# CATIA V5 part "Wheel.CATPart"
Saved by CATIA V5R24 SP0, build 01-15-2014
Part number: Wheel
Bounding box of the stored display mesh (mm): x -49.986 to 49.986, y -49.986 to 49.986, z -22.5 to 22.5
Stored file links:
  \\cdl-main\FTPSERVER\Minsik\2016\2\Wheel.CATPart
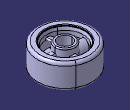
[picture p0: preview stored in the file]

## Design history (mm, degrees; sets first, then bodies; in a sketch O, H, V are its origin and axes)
Set1
  Sketch1 on yz-plane, origin (0, 0, 0), H (0, 1, 0), V (0, 0, 1)
    axis line L1 (0, 45.4444) -> (0, -46.7173)
    point P1 (0, 45.4444)
    point P3 (32, -5.5)
    line L2 (32, -5.5) -> (32, -18)
    line L3 (32, -18) -> (34, -18)
    line L4 (34, -18) -> (34, -21.4393)
    line L5 (35.0607, -22.5) -> (45, -22.5)
    line L6 (50, -17.5) -> (50, 17.5)
    line L7 (45, 22.5) -> (37.5, 22.5)
    line L8 (36.5, 21.5) -> (36.5, 20.5)
    line L9 (36.5, 20.5) -> (35.5, 20.5)
    point P7 (35.5, 20.5)
    line L10 (35.5, 20.5) -> (33.5, 15.5)
    point P8 (33.5, 15.5)
    line L11 (33.5, 15.5) -> (33.5, 7.5)
    point P9 (33.5, 7.5)
    line L12 (33.5, 7.5) -> (32, -5.5)
    arc A1 centre (45, 17.5) radius 5 from (45, 22.5) to (50, 17.5) cw
    arc A2 centre (45, -17.5) radius 5 from (50, -17.5) to (45, -22.5) cw
    arc A3 centre (37.5, 21.5) radius 1 from (37.5, 22.5) to (36.5, 21.5) ccw
    line L13 (34, -21.4393) -> (35.0607, -22.5)
    distance L5 L7 = 45
    distance L6 V = 50
    distance L11 V = 33.5
    distance L7 L9 = 2
    length L9 = 1
    distance L11 P7 = 2
    distance L9 P8 = 5
    distance L3 L5 = 4.5
    distance L7 P9 = 15
    distance P9 P3 V = 13
    distance L2 L4 = 2
    radius A1 = 5
    radius A2 = 5
    radius A3 = 1
    angle L4 L13 = 45
    length L13 = 1.5
    distance L2 V = 32
    coincidence: P1 V
    vertical: L1 V, L2 V, L4 V, L6 V, L8 V, L11 V
    horizontal: L3 H, L5 H, L7 H, L9 H
    symmetry: L7 L5 H
    tangency: A1 L7, A1 L6, A2 L6, A2 L5, A3 L7, A3 L8
Body1 (main body)
  Shaft1: profile Sketch1, axis Sketch1.L1, angle 360
  Sketch2 on xy-plane, origin (0, 0, 0), H (1, 0, 0), V (0, 1, 0)
    circle A1 centre (0, 0) radius 18
    circle A2 centre (0, 0) radius 12.5
    radius A1 = 18
    radius A2 = 12.5
  Pad1: profile Sketch2, direction (0, 0, 1), length 22.5, mirrored extent
  Fillet1: radius 2, on edge [face of Pad1 from Sketch2.A1 | end face of Pad1]
  Sketch3 on xy-plane, origin (0, 0, 0), H (1, 0, 0), V (0, 1, 0)
    circle A1 centre (0, 0) radius 40
    circle A2 centre (0, 0) radius 14
    radius A1 = 40
    radius A2 = 14
  Pad2: profile Sketch3, direction (0, 0, 1), length -5.5, opposite side length 14
  Sketch4 on start face of Pad2, origin (0, 0, -14), H (1, 0, 0), V (0, -1, 0)
    construction arc A1 centre (3, 10) radius 20 from (-3, 29.0788) to (-16.5, 14.4441) ccw
    point P1 (3, 10)
    point P2 (-3, 29.0788)
    point P3 (-16.5, 14.4441)
    arc A2 centre (-3, 29.0788) radius 1.5 from (-3.45, 30.5097) to (-2.55, 27.6479) cw
    arc A3 centre (-16.5, 14.4441) radius 1.5 from (-15.0375, 14.1108) to (-17.9625, 14.7774) cw
    arc A4 centre (3, 10) radius 18.5 from (-2.55, 27.6479) to (-15.0375, 14.1108) ccw
    arc A5 centre (3, 10) radius 21.5 from (-17.9625, 14.7774) to (-3.45, 30.5097) cw
    radius A3 = 1.5
    distance P2 V = 3
    radius A5 = 21.5
    distance P1 H = 10
    distance P1 V = 3
    distance P3 V = 16.5
    tangency: A4 A3, A3 A5, A5 A2, A2 A4
    concentricity: A4 P1, A5 P1
  Pocket1: profile Sketch4, direction (0, 0, 1), through (limit type 6)
  CircPattern1: of Pocket1, instances 7, angular step 60, axis from start face of Pad2
  Body2
    Sketch5 on yz-plane, origin (0, 0, 0), H (0, 1, 0), V (0, 0, -1)
      construction arc A1 centre (0, 4) radius 13.5 from (0, -9.5) to (13.4164, 2.5) ccw
      point P1 (0, 4)
      point P2 (0, -9.5)
      point P3 (13.4164, 2.5)
      arc A2 centre (0, -9.5) radius 2 from (0, -11.5) to (0, -7.5) cw
      arc A3 centre (13.4164, 2.5) radius 2 from (11.4288, 2.7222) to (15.404, 2.2778) cw
      arc A4 centre (0, 4) radius 11.5 from (0, -7.5) to (11.4288, 2.7222) ccw
      arc A5 centre (0, 4) radius 15.5 from (15.404, 2.2778) to (0, -11.5) cw
      construction line L1 (0, 4) -> (13.4164, 2.5)
      construction line L2 (0, -9.5) -> (0, 4)
      reference projected line E1 (-45, -22.5) -> (45, -22.5) from edge [face of Shaft1 from Sketch1.L7 | face of Shaft1 from Sketch1.A1]
      radius A3 = 2
      radius A5 = 15.5
      distance P2 P3 V = 12
      distance E1 A5 = 11
      tangency: A4 A3, A3 A5, A5 A2, A2 A4
      concentricity: A4 P1, A5 P1
      coincidence: P2 V, L2 V
    Pad3: profile Sketch5, direction (1, 0, 0), length -61
    CircPattern2: of the body so far, instances 4, angular step 90, axis from face of Shaft1 from Sketch1.L7
  Trim1: tool Body2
